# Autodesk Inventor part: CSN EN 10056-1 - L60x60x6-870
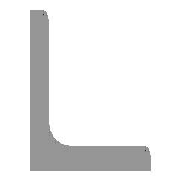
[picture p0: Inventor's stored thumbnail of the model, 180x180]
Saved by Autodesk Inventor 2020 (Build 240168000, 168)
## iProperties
Created: 2019-01
Part Number: CSN EN 10056-1 - L60x60x6-870
Material: Ocel, měkká
Description: Za tepla válcovaný konstrukcní ocelový profil - Rovnoramenné L2
Document SubType Name: Modeling
Standard: CSN EN 10056-1
Designer: doma
Standards Organization: CSN
Language: cs-CZ
Size Designation: L60x60x6-870
Categories: <MemberInstance><Categories><Category DisplayName="Konstrukční profily" InternalName="089c4875-fa83-4c05-b084-43b9cc11f5ed" Mnemonic="GRDR"><CategoryParameter D
Stock Number: L60x60x6
Density: 7.85 g/cm^3
Appearance: Pololeštěná
IsCustomPart: 1
G_L: 870,000 mm
Author: doma
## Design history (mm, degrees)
node "Počáteční rovina"
node "Koncová rovina"
sketch "Náčrt2"
  geometry: L1 (-10.873, -2.873)-(-10.873, 39.127); L2 (-16.873, 43.127)-(-14.873, 43.127); L3 (-16.873, -16.873)-(-16.873, 43.127); L4 (-16.873, -16.873)-(43.127, -16.873); L5 (43.127, -14.873)-(43.127, -16.873); L6 (-2.873, -10.873)-(39.127, -10.873); L7 (0, 60.87)-(0, -10.145) reference; L8 (-10.145, 0)-(60.87, 0) reference; A1 r 8 centre (-2.873, -2.873) between (-10.873, -2.873) and (-2.873, -10.873); A2 r 4 centre (-14.873, 39.127) between (-10.873, 39.127) and (-14.873, 43.127); A3 r 4 centre (39.127, -14.873) between (43.127, -14.873) and (39.127, -10.873); 3 further points
  constraints: 12 end point, 6 point on circle, 6 point on line, 6 tangent, 3 centre point, 3 horizontal, 3 vertical, 1 equal radius
  dimensions: "d4" = 60 distance of L3.start L4.end (= b); "d6" = 60 distance of L3.start L2.start (= b); "d8" = 6 distance of point (43.127, -10.873) L4.end (= ParT); "d10" = 6 distance of L2.start point (-10.873, 43.127) (= ParT); "d17" = 8 radius of A1 (= R); "d18" = 4 radius of A2 (= R1); "d19" = 16.87307 distance between parallel lines of L8 L4 (= ex); "d20" = 16.87307 distance between parallel lines of L3 L7 (= d19)
extrude "Těleso" new body sketch "Náčrt2" stored distance "d11" = 870 (= G_L); taper "d12" = 0 deg
node "Driven Length"
  sketch "Sketch3"
    geometry: L1 (0, 0)-(10, 0) reference
    constraints: 2 end point, 1 horizontal
  workplane "Work Plane10"
  sketch "Sketch4"
    geometry: L1 (-2, 0)-(12, 0) reference; L2 (-2, 870)-(12, 870) reference
    dimensions: "d24" = 870 distance between parallel lines of L1 L2 (derived)
sketch "Náčrt5"
  geometry: L1 (0, 0)-(94.754, 94.754); L2 (0, 0)-(134.002, 0); L3 (94.754, 94.754)-(144.155, -96.623); L4 (144.155, -96.623)-(-96.623, -96.623); L5 (-96.623, -96.623)-(0, 0); L6 (0, 870)-(180.047, 689.953); L7 (180.047, 689.953)-(225.912, 956.935); L8 (225.912, 956.935)-(0, 870); 1 further point
  constraints: 16 end point, 2 horizontal, 1 collinear, 1 equal length, 1 point on line
  dimensions: "d25" = 45 deg angle of L2 L1
extrude "Vysunutí2" cut sketch "Náčrt5" extent not by distance; stored distance "d26" = 0; taper "d27" = 0 deg
chamfer "Zkosení1" distance "d28" = 3; stored, may be unused: second distance "d29" = 2, angle "d30" = 45 deg
body "Solid1"
other parameters: "b" = 60 [user parameter; used in 3 equation terms], "ParT" = 6 [user parameter; used in 3 equation terms], "R" = 8 [user parameter; used in 1 equation term], "R1" = 4 [user parameter; used in 1 equation term], "G_L" = 870 (= d24) [user parameter; used in 1 equation term], "d7" = 4 (derived), "d9" = 4 (derived), "ex" = 16.87307 (computed from b, ParT) [user parameter; used in 1 equation term], "G_OFFSET_START" = 0 [user parameter; used in 1 equation term], "G_OFFSET_END" = 0 [user parameter; used in 1 equation term], "d21" = 0 (computed from G_OFFSET_START), "d23" = 90 deg
